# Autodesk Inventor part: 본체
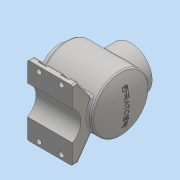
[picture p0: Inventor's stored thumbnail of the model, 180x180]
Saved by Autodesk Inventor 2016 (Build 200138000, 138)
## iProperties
Created: 2021-04
Part Number: 본체
Material: Generic
Document SubType Name: Modeling
Designer: User
Density: 1 g/cm^3
Appearance: Default
Author: User
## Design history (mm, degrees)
sketch "스케치2"
  geometry: L1 (-71.647, 0)-(96.782, 0); L2 (-33.773, 50)-(62.564, 50); L3 (-33.773, 50)-(-33.773, 38); L4 (-33.773, 38)-(-45.773, 38); L5 (-45.773, 38)-(-45.773, 0); A1 r 113 centre (-38.773, 0) between (74.227, 0) and (62.564, 50); 1 further point
  constraints: 10 end point, 3 horizontal, 3 point on line, 2 point on circle, 1 centre point, 1 perpendicular
  dimensions: "d0" = 100 diameter of L2 L1; "d1" = 76 diameter of L4 L1; "d5" = 12 distance of L3.end L4.end; "d6" = 226 diameter of A1; "d7" = 108 distance from line of A1.start L3
revolve "회전1" sketch "스케치2" stored, may be unused: angle "d2" = 90 deg
node "작업 평면1"
sketch "스케치3"
  geometry: L1 (-62, -77)-(-62, -67); L2 (62, -77)-(62, -67); L3 (62, -67)-(14.694, -33.876); L4 (-62, -67)-(-14.694, -33.876); L5 (-14.694, -33.876)-(14.694, -33.876); L6 (0, 0)-(50, 0.171); L7 (-62, -77)-(-25.981, -77); L8 (25.981, -77)-(62, -77); L9 (-25.981, -77)-(25.981, -77); L10 (0, 0)-(0, -77); A1 r 30 centre (0, -92) between (25.981, -77) and (-25.981, -77); 1 further point
  constraints: 20 end point, 4 horizontal, 2 parallel, 2 point on circle, 1 centre point, 1 collinear, 1 midpoint, 1 vertical
  dimensions: "d11" = 124 distance of L1.start L2.start; "d12" = 55 deg angle of L2 L3; "d13" = 10 distance of L2.start L2.end; "d15" = 77 distance of L6.start L10.end
extrude "돌출1" join sketch "스케치3" distance "d16" = 80; taper "d17" = 0 deg
node "작업 평면2"
sketch "스케치4"
  geometry: L1 (-8, -63.981)-(-8, 12.019) reference; L2 (-20, -63.981)-(-20, 12.019) reference; C1 r 38 at (42, -25.981); 1 further point
  constraints: 1 centre point
  dimensions: "d19" = 62 distance from line of C1.centre L2
extrude "돌출2" join sketch "스케치4" stored distance "d20" = 80; taper "d21" = 0 deg
sketch "스케치5"
  geometry: 1 further point
hole "구멍1" diameter "d24" = 54; stored, may be unused: countersink angle "d28" = 90 deg, drill point angle "d30" = 118 deg; dims "d22" = 10, "d23" = 10, "d25" = 6, "d26" = 4, "d27" = 2, "d29" = 40
sketch "스케치6"
  geometry: L1 (-33.773, -38)-(-33.773, 38) reference; L2 (-45.773, -38)-(-45.773, 38) reference; L3 (62.564, -50)-(62.564, 50) reference; L4 (56.163, -1.923)-(56.163, 0); L5 (56.163, 40)-(-23.773, 40); L6 (-23.773, 40)-(-23.773, 0); L7 (-23.773, 0)-(63.528, 0); L8 (-33.773, -50)-(-33.773, 50) reference; L9 (-33.773, 50)-(62.564, 50) reference; A1 r 113 centre (-38.773, 0) between (62.564, -50) and (62.564, 50) reference; A2 r 112.301 centre (-48.773, 0) between (63.528, 0) and (56.163, 40); 1 further point
  constraints: 8 end point, 2 point on circle, 1 centre point, 1 horizontal, 1 parallel, 1 point on line
  dimensions: "d31" = 10 distance of A1.centre A2.centre; "d32" = 10 distance between parallel lines of L6 L8; "d33" = 10 distance between parallel lines of L5 L9
revolve "회전2" sketch "스케치6" stored, may be unused: angle "d34" = 90 deg
hole "구멍2" diameter "d37" = 54; stored, may be unused: countersink angle "d41" = 90 deg, drill point angle "d43" = 0 deg; dims "d35" = 10, "d36" = 10, "d38" = 6, "d39" = 4, "d40" = 2, "d42" = 25
fillet "모깎기1" dims "d44" = 3
fillet "모깎기2" dims "d45" = 3
fillet "모깎기3" dims "d46" = 3
node "작업 평면3"
sketch "스케치7"
  geometry: L1 (80, -51.962)-(80, -84.981) reference; L2 (0, -51.962)-(80, -51.962) reference; L3 (0, -51.962)-(0, -84.981) reference; L4 (3, -87.981)-(77, -87.981) reference; L5 (3, 36.019)-(77, 36.019) reference; L6 (0, 33.019)-(0, 0) reference; L7 (0, 0)-(80, 0) reference; L8 (80, 33.019)-(80, 0) reference; L9 (25.773, -25.981)-(112.863, -25.981); L10 (53, 28.019)-(53, 48.493); L11 (53, 48.493)-(67, 48.493); L12 (67, 48.493)-(67, 28.019); L13 (13, 28.019)-(13, 49.686); L14 (13, 49.686)-(27, 49.686); L15 (27, 49.686)-(27, 28.019); L16 (13, -79.981)-(13, -96.968); L17 (13, -96.968)-(27, -96.968); L18 (27, -96.968)-(27, -79.981); L19 (53, -79.981)-(53, -96.968); L20 (53, -96.968)-(67, -96.968); L21 (67, -96.968)-(67, -79.981); A1 r 3 centre (77, -84.981) between (77, -87.981) and (80, -84.981) reference; A2 r 3 centre (3, -84.981) between (0, -84.981) and (3, -87.981) reference; A3 r 3 centre (77, 33.019) between (80, 33.019) and (77, 36.019) reference; A4 r 3 centre (3, 33.019) between (3, 36.019) and (0, 33.019) reference; A5 r 7 centre (60, -79.981) between (67, -79.981) and (53, -79.981); A6 r 7 centre (20, -79.981) between (27, -79.981) and (13, -79.981); A7 r 7 centre (20, 28.019) between (13, 28.019) and (27, 28.019); A8 r 7 centre (60, 28.019) between (53, 28.019) and (67, 28.019); 4 further points
  constraints: 26 end point, 8 point on circle, 4 centre point, 4 coincident, 4 parallel, 3 point on line, 2 symmetric about line, 1 horizontal
  dimensions: "d48" = 54 vertical distance of L9.start point (60, -79.981); "d49" = 20 distance from line of point (60, -79.981) L1; "d50" = 40 distance of point (20, -79.981) point (60, -79.981); "d51" = 14 diameter of A5; "d52" = 14 diameter of A6; "d53" = 14 diameter of A7; "d54" = 14 diameter of A8
extrude "돌출3" cut sketch "스케치7" distance "d55" = 20; taper "d56" = 0 deg
sketch "스케치8"
  geometry: L1 (53, -79.981)-(53, -86.701) reference; L2 (27, -86.701)-(53, -86.701) reference; L3 (27, -86.701)-(27, -79.981) reference; L4 (13, -79.981)-(13, -86.701) reference; L5 (3, -86.701)-(13, -86.701) reference; L6 (3, -56.204)-(3, -86.701) reference; L7 (77, -56.204)-(3, -56.204) reference; L8 (77, -86.701)-(77, -56.204) reference; L9 (67, -86.701)-(77, -86.701) reference; L10 (67, -86.701)-(67, -79.981) reference; L11 (27, 28.019)-(27, 34.74) reference; L12 (53, 34.74)-(27, 34.74) reference; L13 (53, 34.74)-(53, 28.019) reference; L14 (67, 28.019)-(67, 34.74) reference; L15 (77, 34.74)-(67, 34.74) reference; L16 (77, 4.242)-(77, 34.74) reference; L17 (3, 4.242)-(77, 4.242) reference; L18 (3, 34.74)-(3, 4.242) reference; L19 (13, 34.74)-(3, 34.74) reference; L20 (13, 34.74)-(13, 28.019) reference; C1 r 4.5 at (60, -79.981); C2 r 4.5 at (20, -79.981); C3 r 4.5 at (60, 28.019); C4 r 4.5 at (20, 28.019); A1 r 7 centre (20, -79.981) between (27, -79.981) and (13, -79.981) reference; A2 r 7 centre (60, -79.981) between (67, -79.981) and (53, -79.981) reference; A3 r 7 centre (60, 28.019) between (53, 28.019) and (67, 28.019) reference; A4 r 7 centre (20, 28.019) between (13, 28.019) and (27, 28.019) reference; 1 further point
  constraints: 4 centre point, 4 coincident
extrude "돌출4" cut sketch "스케치8" distance "d57" = 20; taper "d58" = 0 deg
fillet "모깎기4" dims "d59" = 3
fillet "모깎기5" dims "d60" = 3
chamfer "모따기1" distance "d61" = 1; stored, may be unused: second distance "d62" = 2, angle "d63" = 45 deg
node "작업 평면5"
  node "작업 평면4"
sketch "스케치9"
  geometry: L1 (29.513, 27)-(65, 27) reference; C1 r 48.282 at (0, 0) reference; 2 further points
  constraints: 1 coincident, 1 other
feature "엠보싱1" sketch "스케치9" dims "d0" = 100, "d1" = 76, "d5" = 12, "d6" = 226, "d7" = 108, "d15" = 77, "d65" = 0.5, "d66" = 0
sketch "스케치11"
  geometry: C1 r 38 at (0, 0) reference; C2 r 28 at (0, 0) reference; A1 r 32.5 centre (0, 0) between (-32.5, 0) and (0, 32.5); 3 further points
  constraints: 4 point on circle, 1 centre point, 1 coincident
hole "구멍3" sketch "스케치11" at (0, 32.5), (32.5, 0), (0, -32.5), (-32.5, 0) diameter "d67" = 3.242; stored, may be unused: countersink angle "d71" = 90 deg, drill point angle "d73" = 118 deg; dims "d68" = 8, "d69" = 4, "d70" = 2, "d72" = 11.8
sketch "스케치12"
  geometry: C1 r 27 at (0, 0) reference; C2 r 38 at (0, 0) reference; A1 r 32.5 centre (0, 0) between (-32.5, 0) and (0, 32.5); 3 further points
  constraints: 4 point on circle, 1 centre point, 1 coincident
hole "구멍4" sketch "스케치12" at (0, 32.5), (32.5, 0), (0, -32.5), (-32.5, 0) diameter "d74" = 3.242; stored, may be unused: countersink angle "d78" = 90 deg, drill point angle "d80" = 118 deg; dims "d75" = 8, "d76" = 4, "d77" = 2, "d79" = 11.8
node "솔리드1"
node "투영된 루프3"
node "투영된 루프4"
node "투영된 루프5"
node "투영된 루프6"
node "투영된 루프7"
node "투영된 루프8"
node "투영된 루프9"
node "투영된 루프10"
node "투영된 루프11"
other parameters: "d14" = 15, "d18" = -142, "d47" = -6, "d64" = 0.5
